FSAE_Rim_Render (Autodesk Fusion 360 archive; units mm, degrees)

design "FSAE Rim" references "Hexagon Nut DIN 934 - M4 x 0.7 Steel 6 Plain", "Hexagon Socket Head Cap Screw DIN 912 - M4 x 0.7 x 16 Steel 4.6 Plain"
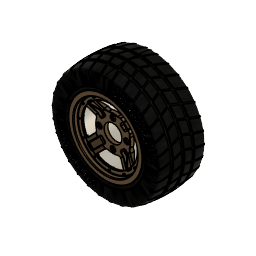
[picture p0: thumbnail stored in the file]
part number: 2026-07-27-09-56-27-671
part number: 2026-08-04-10-59-52-273
part number: 2026-08-04-10-59-52-284
part number: 2026-08-04-10-59-52-289
sketch "Sketch1" plane through (0, 0, 0) normal (1, 0, 0) x axis (0, 1, 0)
  line L1 (153.5, 0) -> (0, 0)
  line L2 (0, 119.5) -> (0, 104)
  line L3 (143.5, 124.5) -> (5, 124.5)
  line L4 (148.5, 134.75) -> (148.5, 129.5)
  line L5 (153.5, 138.25) -> (152, 138.25)
  line L6 (2.5, 119.5) -> (2.5, 104)
  line L7 (143.5, 122) -> (5, 122)
  line L8 (151, 134.75) -> (151, 129.5)
  line L9 (153.5, 135.75) -> (152, 135.75)
  line L10 (2.5, 104) -> (0, 104)
  line L11 (153.5, 135.75) -> (153.5, 138.25)
  arc A1 centre (152, 134.75) radius 3.5 clockwise from (148.5, 134.75) to (152, 138.25)
  arc A2 centre (143.5, 129.5) radius 5 clockwise from (148.5, 129.5) to (143.5, 124.5)
  arc A3 centre (5, 119.5) radius 5 clockwise from (0, 119.5) to (5, 124.5)
  arc A4 centre (5, 119.5) radius 2.5 clockwise from (2.5, 119.5) to (5, 122)
  arc A5 centre (143.5, 129.5) radius 7.5 clockwise from (151, 129.5) to (143.5, 122)
  arc A6 centre (152, 134.75) radius 1 clockwise from (151, 134.75) to (152, 135.75)
  point P1 (0, 0)
  point P2 (0, 0)
  point P4 (0, 104)
  point P3 (153.5, 0)
  point P7 (153.5, 138.25)
  point P6 (148.5, 124.5)
  point P5 (0, 124.5)
  coincident P1 P2
  horizontal L1
  perpendicular L1 L2
  perpendicular L2 L3
  perpendicular L3 L4
  perpendicular L4 L5
  vertical P1 P4
  vertical P3 P7
  tangent L4 A1
  tangent L5 A1
  coincident P6 L3
  coincident P6 L4
  tangent L3 A2
  tangent L4 A2
  coincident P5 L2
  coincident P5 L3
  tangent L2 A3
  tangent L3 A3
  equal A2 A3
  perpendicular L6 L10
  perpendicular L9 L11
  dimension "d1" distance P2 P3 = 153.5
  dimension "d2" = 208
  dimension "d3" = 249
  dimension "d4" = 276.5
  dimension "d5" distance P5 P6 = 148.5
  dimension "d6" radius A1 = 3.5
  dimension "d7" radius A2 = 5
  dimension "d8" = 2.5
revolve "Revolve1" sketch "Sketch1" AlongAngle 360 bodies "FSAE Rim Back"
sketch "Sketch2" plane through (0, 0, 0) normal (0, -1, 0) x axis (1, 0, 0)
  circle C1 centre (0, 0) radius 104
  circle C2 centre (0, 0) radius 119.5
  circle C3 centre (0, 0) radius 112
  circle C4 centre (0, 112) radius 2.15
  point P1 (0, 0)
  point P3 (0, 0)
  point P4 (0, 112)
  coincident P1 P3
  coincident C3 P4
  vertical P3 P4
  dimension "d10" diameter C3 = 224
  dimension "d11" diameter C4 = 4.3
extrude "Extrude1" cut sketch "Sketch2" profile of C4 to an object
circular_pattern "C-Pattern1" TotalAngle 360
canvas "Canvas1"
move "Move1"
sketch "Sketch4" plane through (0, 0, 0) normal (1, 0, 0) x axis (0, 1, 0)
  line L1 (14, 0) -> (0, 0)
  line L2 (14, 72.5) -> (14, 0)
  line L3 (-8, 102.5) -> (14, 72.5)
  line L4 (-8, 124.5) -> (-8, 102.5)
  line L5 (-23.5, 124.5) -> (-8, 124.5)
  line L6 (-23.5, 138) -> (-23.5, 124.5)
  line L7 (-28.25, 138) -> (-23.5, 138)
  line L8 (-28.25, 0) -> (-28.25, 138)
  line L9 (0, 0) -> (-28.25, 0)
  line L10 (-13, 118.1658) -> (-28.25, 119.5)
  line L11 (-13, 102.5) -> (-13, 118.1658)
  line L12 (0, 68.6338) -> (-13, 102.5)
  line L13 (0, 0) -> (0, 68.6338)
  point P1 (0, 0)
  point P2 (0, 0)
  point P11 (0, 0)
  point P12 (-28.25, 119.5)
  point P5 (-8, 102.5)
  point P14 (-13, 102.5)
  point P3 (14, 0)
  point P4 (14, 72.5)
  point P6 (-8, 124.5)
  point P8 (-23.5, 138)
  point P9 (-28.25, 138)
  coincident P1 P2
  horizontal L1
  perpendicular L1 L2
  perpendicular L1 L4
  perpendicular L4 L5
  perpendicular L5 L6
  perpendicular L6 L7
  coincident P1 P11
  collinear L1 L9
  perpendicular L8 L9
  coincident L8 P12
  parallel L8 L11
  vertical L13
  horizontal P5 P14
  dimension "d29" distance P2 P3 = 14
  dimension "d30" = 145
  dimension "d31" = 205
  dimension "d32" = 249
  dimension "d33" = 276
  dimension "d34" distance P4 P6 = 22
  dimension "d35" distance P6 P8 = 15.5
  dimension "d36" distance P8 P9 = 4.75
  dimension "d37" distance L4 L11 = 5
  dimension "d38" angle L12 L13 = 159
  dimension "d39" angle L10 L11 = 95
  dimension "d40" = 239
revolve "Revolve3" sketch "Sketch4" AlongAngle 360 bodies "FSAE Rim Front"
sketch "Sketch5" plane through (0, 0, 0) normal (0, -1, 0) x axis (1, 0, 0)
  circle C1 centre (0, 0) radius 68.6338
  circle C2 centre (0, 0) radius 33
  point P1 (0, 0)
  point P3 (0, 0)
  coincident P1 P3
  dimension "d42" diameter C2 = 66
extrude "Extrude2" cut sketch "Sketch5" profile of C2 to an object
sketch "Sketch6" plane through (0, 0, 0) normal (0, -1, 0) x axis (1, 0, 0)
  circle C1 centre (0, 0) radius 33
  circle C2 centre (0, 0) radius 68.6338
  circle C3 centre (0, 0) radius 50.8
  point P1 (0, 0)
  point P4 (0, 0)
  point P3 (0, 50.8)
  coincident P1 P4
  coincident P3 C3
  vertical P1 P3
  dimension "d45" diameter C3 = 101.6
hole "Hole1" HoleDiameter 10.5 TipAngle 180 CBDepth 5 CBDiameter 20
chamfer "Chamfer2" sketch "Sketch1" distance 0.5
circular_pattern "C-Pattern2" TotalAngle 360
sketch "Sketch7" plane through (0, -13, 0) normal (0, -1, 0) x axis (1, 0, 0)
  circle C1 centre (0, 0) radius 102.5
  circle C2 centre (0, 0) radius 118.1658
  circle C3 centre (0, 0) radius 112
  point P1 (0, 0)
  point P3 (0, 0)
  point P4 (0, 112)
  coincident P1 P3
  coincident C3 P4
  vertical P1 P4
  dimension "d53" diameter C3 = 224
hole "Hole2" HoleDiameter 4.3 TipAngle 180
circular_pattern "C-Pattern3" TotalAngle 360
fillet "Fillet1" radius 1 3 2
chamfer "Chamfer1" distance 0.5
form "Form1" bodies "Tire"
fillet "Fillet2" radius 5
sketch "Sketch8" plane through (0, 0, 0) normal (1, 0, 0) x axis (0, 1, 0)
  line L1 (47.5, 224.911) -> (47.5, 204.911)
  line L2 (57.5, 224.911) -> (47.5, 224.911)
  line L3 (57.5, 204.9943) -> (57.5, 224.911)
  line L4 (87.5, 224.911) -> (87.5, 204.2438)
  line L5 (97.5, 224.911) -> (87.5, 224.911)
  line L6 (97.5, 203.6595) -> (97.5, 224.911)
  line L7 (17.5, 224.911) -> (17.5, 203.6595)
  line L8 (7.5, 224.911) -> (17.5, 224.911)
  line L9 (7.5, 202.9073) -> (7.5, 224.911)
  arc A1 centre (57.5, -395.0057) radius 600 clockwise from (-46, 196) to (161, 196)
  point P2 (-46, 196)
  point P3 (161, 196)
  point P8 (57.5, 204.9943)
  point P9 (87.5, 204.2438)
  point P12 (97.5, 203.6595)
  point P13 (17.5, 203.6595)
  point P16 (7.5, 202.9073)
  point P5 (47.5, 204.911)
  point P1 (0, 0)
  point P6 (47.5, 224.911)
  point P7 (57.5, 224.911)
  horizontal P2 P3
  vertical L1
  perpendicular L1 L2
  midpoint A1 P8
  perpendicular L2 L3
  coincident A1 P9
  parallel L3 L4
  perpendicular L4 L5
  coincident A1 P12
  perpendicular L5 L6
  coincident A1 P13
  perpendicular L5 L7
  perpendicular L7 L8
  coincident A1 P16
  perpendicular L8 L9
  collinear L2 L8
  collinear L2 L5
  equal L2 L8
  equal L2 L5
  coincident A1 P5
  dimension "d68" radius A1 = 600
  dimension "d69" distance P1 P3 = 196
  dimension "d70" distance P1 P2 = 46
  dimension "d71" distance P1 P3 = 161
  dimension "d73" distance P6 P7 = 10
  dimension "d74" distance L1 L7 = 30
  dimension "d75" distance L3 L4 = 30
  dimension "d76" distance P5 P6 = 20
revolve "Revolve4" AlongAngle 360
revolve "Revolve5" sketch "Sketch8" AlongAngle 360
work_plane "WorkPlane1" AlongDistance 275 ExtraOffset 0
sketch "Sketch9" plane through (0, 0, 275) normal (0, 0, 1) x axis (1, 0, 0)
  line L1 (-48.7008, 53.5011) -> (0, -75.7953)
  line L2 (0, 197.5142) -> (-48.7008, 53.5011)
  line L3 (-43.392, 53.5917) -> (4.6791, -74.0329)
  line L4 (4.7365, 195.9124) -> (-43.392, 53.5917)
  line L5 (4.6791, -74.0329) -> (0, -75.7953)
  line L6 (0, 197.5142) -> (4.7365, 195.9124)
  perpendicular L3 L5
  perpendicular L2 L6
  dimension "d80" = 5
step "SurfaceExtend" extendDistance 125
extrude "Extrude3" cut sketch "Sketch9" to an object
circular_pattern "C-Pattern4" countU 30 TotalAngle 360
remove_body "RemoveBody1"
remove_body "RemoveBody2"
work_plane "WorkPlane2" AlongDistance -150 ExtraOffset 0
sketch "Sketch10" plane through (0, -150, 0) normal (0, 1, 0) x axis (1, 0, 0)
  circle C1 centre (0, 0) radius 157.5
  point P1 (0, 0)
  point P2 (0, 0)
  coincident P1 P2
  dimension "d88" diameter C1 = 315
  dimension "d89" Text1-Height = 20
extrude "Extrude4" sketch "Sketch10" blind 2
circular_pattern "C-Pattern5" TotalAngle 360
component_from_bodies "Body->Comp1"
component_from_bodies "Body->Comp2"
component_from_bodies "Body->Comp3"
sketch "Sketch1" plane through (0, -13, 0) normal (0, -1, 0) x axis (1, 0, 0)
  line L1 (0, 103.056) -> (0, 0)
  line L2 (103.056, 0) -> (0, 0)
  line L3 (72.8716, 72.8716) -> (0, 0)
  line L4 (88.3726, 53.0172) -> (60.1041, 24.7487)
  line L5 (53.0172, 88.3726) -> (24.7487, 60.1041)
  circle C1 centre (0, 0) radius 103.056
  circle C2 centre (0, 112) radius 2.15
  circle C3 centre (56, 96.9948) radius 2.15
  circle C4 centre (96.9948, 56) radius 2.15
  circle C5 centre (112, 0) radius 2.15
  circle C6 centre (96.9948, -56) radius 2.15
  circle C7 centre (56, -96.9948) radius 2.15
  circle C8 centre (0, -112) radius 2.15
  circle C9 centre (-56, -96.9948) radius 2.15
  circle C10 centre (-96.9948, -56) radius 2.15
  circle C11 centre (-112, 0) radius 2.15
  circle C12 centre (-96.9948, 56) radius 2.15
  circle C13 centre (-56, 96.9948) radius 2.15
  circle C14 centre (0, 0) radius 116.3331
  arc A1 centre (0, 0) radius 65 clockwise from (0, 65) to (65, 0)
  arc A2 centre (0, 0) radius 65 clockwise from (65, 0) to (0, 65)
  point P2 (0, 0)
  point P16 (0, 0)
  point P17 (0, 103.056)
  point P18 (103.056, 0)
  point P15 (0, 0)
  point P19 (0, 0)
  point P20 (72.8716, 72.8716)
  point P22 (24.7487, 60.1041)
  point P21 (60.1041, 24.7487)
  point P23 (53.0172, 88.3726)
  point P24 (88.3726, 53.0172)
  point P25 (0, 65)
  point P26 (65, 0)
  concentric C1 A1
  coincident P2 P16
  coincident C1 P17
  vertical L1
  coincident C1 P18
  perpendicular L1 L2
  coincident P15 P19
  coincident C1 P20
  coincident P22 A1
  coincident P21 A1
  coincident C1 P23
  coincident C1 P24
  coincident L1 P25
  coincident L2 P26
  concentric A1 A2
  dimension "d95" diameter A1 = 130
  dimension "d96" angle L1 L3 = 45
extrude "Extrude1" cut sketch "Sketch1" profile of C1 L1 L2 L4 L5 A1 to an object
circular_pattern "C-Pattern1" TotalAngle 360
sketch "Sketch2" plane through (0, -13, 0) normal (0, -1, 0) x axis (1, 0, 0)
  line L1 (72.8716, 72.8716) -> (0, 0)
  line L2 (65.9862, 82.9568) -> (25.8367, 42.8073)
  line L3 (82.9568, 65.9862) -> (42.8073, 25.8367)
  arc A1 centre (0, 0) radius 103.056 clockwise from (-53.0172, 88.3726) to (53.0172, 88.3726)
  arc A2 centre (0, 0) radius 103.056 clockwise from (53.0172, 88.3726) to (88.3726, 53.0172)
  arc A3 centre (0, 0) radius 103.056 clockwise from (88.3726, 53.0172) to (88.3726, -53.0172)
  arc A4 centre (0, 0) radius 103.056 clockwise from (88.3726, -53.0172) to (53.0172, -88.3726)
  arc A5 centre (0, 0) radius 103.056 clockwise from (53.0172, -88.3726) to (-53.0172, -88.3726)
  arc A6 centre (0, 0) radius 103.056 clockwise from (-53.0172, -88.3726) to (-88.3726, -53.0172)
  arc A7 centre (0, 0) radius 103.056 clockwise from (-88.3726, -53.0172) to (-88.3726, 53.0172)
  arc A8 centre (0, 0) radius 103.056 clockwise from (-88.3726, 53.0172) to (-53.0172, 88.3726)
  circle C1 centre (0, 112) radius 2.15
  circle C2 centre (56, 96.9948) radius 2.15
  circle C3 centre (96.9948, 56) radius 2.15
  circle C4 centre (112, 0) radius 2.15
  circle C5 centre (96.9948, -56) radius 2.15
  circle C6 centre (56, -96.9948) radius 2.15
  circle C7 centre (0, -112) radius 2.15
  circle C8 centre (-56, -96.9948) radius 2.15
  circle C9 centre (-96.9948, -56) radius 2.15
  circle C10 centre (-112, 0) radius 2.15
  circle C11 centre (-96.9948, 56) radius 2.15
  circle C12 centre (-56, 96.9948) radius 2.15
  circle C13 centre (0, 0) radius 116.3331
  circle C14 centre (0, 0) radius 50
  circle C15 centre (0, 0) radius 106
  point P23 (0, 0)
  point P25 (0, 0)
  point P27 (25.8367, 42.8073)
  point P28 (42.8073, 25.8367)
  point P29 (82.9568, 65.9862)
  point P30 (65.9862, 82.9568)
  parallel L1 L2
  parallel L1 L3
  coincident P23 P25
  concentric C14 C15
  coincident C14 P27
  coincident C14 P28
  coincident C15 P29
  coincident C15 P30
  dimension "d103" distance L1 L2 = 12
  dimension "d104" distance L1 L3 = 12 (= "d103")
  dimension "d105" diameter C14 = 100
  dimension "d106" diameter C15 = 212
extrude "Extrude2" cut sketch "Sketch2" profile of A2 L2 L3 C14 C15 to an object offset 2
fillet "Fillet1" radius 5
fillet "Fillet2" radius 10
fillet "Fillet3" radius 2
circular_pattern "C-Pattern2" TotalAngle 360
fillet "Fillet4" radius 15 5
chamfer "Chamfer1" sketch "Sketch1" distance 1
step "Screw1"
joint "Assemble" alignAngle 0 alignOffsetX 0 alignOffsetY 0 alignOffsetZ 0
step "Screw2"
joint "Assemble" alignAngle 0 alignOffsetX 0 alignOffsetY 0 alignOffsetZ 0
step "Screw3"
joint "Assemble" alignAngle 0 alignOffsetX 0 alignOffsetY 0 alignOffsetZ 0
step "Screw4"
joint "Assemble" alignAngle 0 alignOffsetX 0 alignOffsetY 0 alignOffsetZ 0
step "Screw5"
joint "Assemble" alignAngle 0 alignOffsetX 0 alignOffsetY 0 alignOffsetZ 0
step "Screw6"
joint "Assemble" alignAngle 0 alignOffsetX 0 alignOffsetY 0 alignOffsetZ 0
step "Screw7"
joint "Assemble" alignAngle 0 alignOffsetX 0 alignOffsetY 0 alignOffsetZ 0
step "Screw8"
joint "Assemble" alignAngle 0 alignOffsetX 0 alignOffsetY 0 alignOffsetZ 0
step "Screw9"
joint "Assemble" alignAngle 0 alignOffsetX 0 alignOffsetY 0 alignOffsetZ 0
step "Screw10"
joint "Assemble" alignAngle 0 alignOffsetX 0 alignOffsetY 0 alignOffsetZ 0
step "Screw11"
joint "Assemble" alignAngle 0 alignOffsetX 0 alignOffsetY 0 alignOffsetZ 0
step "Screw12"
joint "Assemble" alignAngle 0 alignOffsetX 0 alignOffsetY 0 alignOffsetZ 0
step "Nut13"
joint "Assemble" alignAngle 0 alignOffsetX 0 alignOffsetY 0 alignOffsetZ 0
step "Nut14"
joint "Assemble" alignAngle 0 alignOffsetX 0 alignOffsetY 0 alignOffsetZ 0
step "Nut15"
joint "Assemble" alignAngle 0 alignOffsetX 0 alignOffsetY 0 alignOffsetZ 0
step "Nut16"
joint "Assemble" alignAngle 0 alignOffsetX 0 alignOffsetY 0 alignOffsetZ 0
step "Nut17"
joint "Assemble" alignAngle 0 alignOffsetX 0 alignOffsetY 0 alignOffsetZ 0
step "Nut18"
joint "Assemble" alignAngle 0 alignOffsetX 0 alignOffsetY 0 alignOffsetZ 0
step "Nut19"
joint "Assemble" alignAngle 0 alignOffsetX 0 alignOffsetY 0 alignOffsetZ 0
step "Nut20"
joint "Assemble" alignAngle 0 alignOffsetX 0 alignOffsetY 0 alignOffsetZ 0
step "Nut21"
joint "Assemble" alignAngle 0 alignOffsetX 0 alignOffsetY 0 alignOffsetZ 0
step "Nut22"
joint "Assemble" alignAngle 0 alignOffsetX 0 alignOffsetY 0 alignOffsetZ 0
step "Nut23"
joint "Assemble" alignAngle 0 alignOffsetX 0 alignOffsetY 0 alignOffsetZ 0
step "Nut24"
joint "Assemble" alignAngle 0 alignOffsetX 0 alignOffsetY 0 alignOffsetZ 0
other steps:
base_feature "Base Feature1" bodies "FSAE Rim Back"
base_feature "Base Feature1" bodies "Tire"
base_feature "Base Feature1" bodies "FSAE Rim Front"
create_component "CreateComponent1"
reparent_decal "ReparentDecal1"
remove_body "RemoveBody3"
create_component "CreateComponent2"
reparent_decal "ReparentDecal2"
remove_body "RemoveBody4"
create_component "CreateComponent3"
reparent_decal "ReparentDecal3"
remove_body "RemoveBody5"
joint_origin "JointOrigin1"
joint_origin "JointOrigin2"
joint_origin "JointOrigin3"
joint_origin "JointOrigin4"
joint_origin "JointOrigin5"
joint_origin "JointOrigin6"
joint_origin "JointOrigin7"
joint_origin "JointOrigin8"
joint_origin "JointOrigin9"
joint_origin "JointOrigin10"
joint_origin "JointOrigin11"
joint_origin "JointOrigin12"
joint_origin "JointOrigin1"
joint_origin "JointOrigin2"
joint_origin "JointOrigin3"
joint_origin "JointOrigin4"
joint_origin "JointOrigin5"
joint_origin "JointOrigin6"
joint_origin "JointOrigin7"
joint_origin "JointOrigin8"
joint_origin "JointOrigin9"
joint_origin "JointOrigin10"
joint_origin "JointOrigin11"
joint_origin "JointOrigin12"
named bodies: "FSAE Rim Back", "FSAE Rim Front", "Tire"

design "Hexagon Socket Head Cap Screw DIN 912 - M4 x 0.7 x 16 Steel 4.6 Plain"
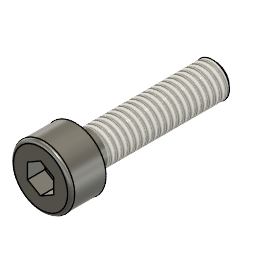
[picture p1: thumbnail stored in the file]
description: Hexagon Socket Head Cap Screw DIN 912 - M4 x 0.7 x 16
part number: DIN 912 - M4 x 0.7 x 16 Steel 4.6 Plain
parameter "adsk_nomlen" = 16
parameter "adsk_headh" = 4
parameter "adsk_headdia" = 7
parameter "adsk_nomdia" = 4
parameter "adsk_philwidth" = 3
parameter "adsk_phildepth" = 2
parameter "adsk_thrlen" = 14.25
parameter "adsk_startlen" = 0.4294
parameter "adsk_endpointdia" = 3.1412
sketch "Sketch1" plane through (0, 0, 0) normal (0, 1, 0) x axis (1, 0, 0)
  line L1 (-2, 16) -> (-2, 0)
  line L2 (0, 16) -> (-2, 16)
  line L3 (0, -4) -> (0, 16)
  line L4 (-3.5, 0) -> (-2, 0)
  line L5 (-3.5, -4) -> (-3.5, 0)
  line L6 (0, -4) -> (-3.5, -4)
  point P1 (0, 0)
  point P4 (0, 16)
  point P7 (0, -4)
  point P5 (-3.5, 0)
  perpendicular L1 L2
  collinear P1 P4 P7
  perpendicular L1 L4
  coincident P1 L4
  vertical L3
  coincident L3 P7
  perpendicular L3 L6
  dimension "d101" distance P1 L2 = 16 (= "adsk_nomlen")
  dimension "d102" distance P5 L6 = 4 (= "adsk_headh")
  dimension "d109" = 7 (= "adsk_headdia")
  dimension "d110" = 4 (= "adsk_nomdia")
revolve "Revolve1" sketch "Sketch1" AlongAngle 360
work_plane "WorkPlane1" AlongDistance 4 (= "adsk_headh")
sketch "Sketch6" plane through (0, 0, 4) normal (0, 0, 1) x axis (1, 0, 0)
  line L1 (1.5, -0.866) -> (0, -1.7321)
  line L2 (1.5, 0.866) -> (1.5, -0.866)
  line L3 (0, 1.7321) -> (1.5, 0.866)
  line L4 (-1.5, 0.866) -> (0, 1.7321)
  line L5 (-1.5, -0.866) -> (-1.5, 0.866)
  line L6 (0, -1.7321) -> (-1.5, -0.866)
  point P1 (0, 0)
  point P8 (0, 0)
  coincident P1 P8
  vertical L2
  dimension "d111" distance L2 L5 = 3 (= "adsk_philwidth")
extrude "Extrude1" cut sketch "Sketch6" no distance stored
extrude "Extrude2" cut of existing geometry no distance stored taper -85
thread "Thread3" ThreadOffset 0 ThreadLength 14.25 (= "min(adsk_thrlen; adsk_nomlen - 0.001 mm)")
fillet "Fillet4" radius 0.4 (= "adsk_nomdia * 0.1")
sketch "Sketch7" plane through (0, 0, 0) normal (0, 1, 0) x axis (1, 0, 0)
  line L1 (-2.04, 15.5706) -> (-2.04, 16)
  line L2 (-1.5706, 16) -> (-2.04, 15.5706)
  line L3 (0, -4) -> (0, 16)
  line L4 (0, 16) -> (-2.04, 16)
  point P5 (0, 16)
  point P7 (0, 16)
  point P4 (-1.5706, 16)
  point P3 (-2.04, 15.5706)
  coincident P5 P7
  perpendicular L3 L4
  coincident P4 L4
  perpendicular L1 L4
  dimension "d104" distance P4 L3 = 1.5706 (= "adsk_endpointdia / 2")
  dimension "d105" distance L1 P7 = 2.04 (= "adsk_nomdia * 0.51")
  dimension "d106" distance P3 L4 = 0.4294 (= "adsk_startlen")
revolve "Revolve3" sketch "Sketch7" AlongAngle 360
joint_origin "JointOrigin2" OffsetX 0 OffsetY 0 OffsetZ 0 AngleZ 0

design "Hexagon Nut DIN 934 - M4 x 0.7 Steel 6 Plain"
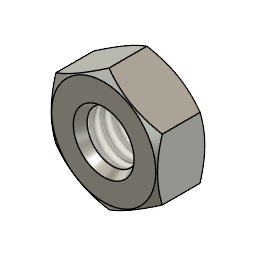
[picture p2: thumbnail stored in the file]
description: Hexagon Nut DIN 934 - M4 x 0.7
part number: DIN 934 - M4 x 0.7 Steel 6 Plain
parameter "adsk_nheig" = 3.2
parameter "adsk_maxdia" = 8.085
parameter "adsk_nomdia" = 4
parameter "adsk_waflat" = 7
parameter "adsk_chamang1" = 30
parameter "adsk_chamang2" = 30
parameter "adsk_beardia" = 6.86 (= "adsk_waflat * 0.98")
sketch "Sketch1" plane through (0, 0, 0) normal (0, 1, 0) x axis (1, 0, 0)
  line L1 (0, -3.2) -> (0, 0)
  line L2 (-3.43, 0) -> (-2, 0)
  line L3 (-4.0425, -0.3536) -> (-3.43, 0)
  line L4 (-4.0425, -2.8464) -> (-4.0425, -0.3536)
  line L5 (-3.43, -3.2) -> (-4.0425, -2.8464)
  line L6 (-2, -3.2) -> (-3.43, -3.2)
  line L7 (-2, 0) -> (-2, -3.2)
  point P3 (0, -3.2)
  point P1 (0, 0)
  point P2 (0, 0)
  point P10 (0, 0)
  point P5 (-3.43, 0)
  point P8 (-3.43, -3.2)
  vertical L1
  coincident L1 P3
  coincident P1 L1
  horizontal L2
  coincident P1 L2
  coincident P2 P10
  coincident P3 L6
  vertical P5 P8
  dimension "d121" = 4 (= "adsk_nomdia")
  dimension "d122" angle L2 L3 = 30 (= "adsk_chamang1")
  dimension "d123" angle L5 L6 = 30 (= "adsk_chamang2")
  dimension "d128" = 8.085 (= "adsk_maxdia")
  dimension "d172" = 6.86 (= "adsk_beardia")
  dimension "d179" distance L2 L6 = 3.2 (= "adsk_nheig")
revolve "Revolve1" sketch "Sketch1" AlongAngle 360
sketch "Sketch8" plane through (0, 0, 3.2) normal (0, 0, 1) x axis (1, 0, 0)
  line L1 (-3.5, 2.0228) -> (-3.5, -2.0228)
  circle C1 centre (0, 0) radius 2
  circle C2 centre (0, 0) radius 4.0425
  point P3 (-3.5, 2.0228)
  point P2 (-3.5, -2.0228)
  point P1 (0, 0)
  coincident P3 C2
  coincident P2 C2
  vertical L1
  dimension "d114" distance P1 L1 = 3.5 (= "adsk_waflat / 2")
extrude "Extrude5" cut sketch "Sketch8" profile of L1 C2 no distance stored
circular_pattern "C-Pattern2" TotalAngle 360
thread "Thread3" ThreadOffset 0 ThreadLength 10
sketch "Sketch12" plane through (0, 0, 0) normal (0, 1, 0) x axis (1, 0, 0)
  line L1 (0, 0) -> (-2, 0)
  line L2 (-2, 0) -> (-1.0762, -1.6)
  line L3 (0, -3.2) -> (-2, -3.2)
  line L4 (-2, -3.2) -> (-1.0762, -1.6)
  line L5 (0, -3.2) -> (0, 0)
  point P4 (-1.0762, -1.6)
  point P7 (-1.0762, -1.6)
  point P2 (-2, 0)
  point P5 (-2, -3.2)
  point P6 (0, -3.2)
  point P9 (0, -3.2)
  point P1 (0, 0)
  point P3 (0, 0)
  horizontal L1
  coincident P4 P7
  vertical P2 P5
  coincident P6 P9
  coincident P1 P3
  perpendicular L3 L5
  dimension "d169" angle L3 L4 = 60
  dimension "d177" distance P2 L5 = 2 (= "adsk_nomdia * 0.5")
  dimension "d178" angle L1 L2 = 60
revolve "Revolve3" sketch "Sketch12" AlongAngle 360
joint_origin "JointOrigin9" OffsetX 0 OffsetY 0 OffsetZ 0 AngleZ 0
joint_origin "JointOrigin10" OffsetX 0 OffsetY 0 OffsetZ 3.2 (= "adsk_nheig") AngleZ 0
